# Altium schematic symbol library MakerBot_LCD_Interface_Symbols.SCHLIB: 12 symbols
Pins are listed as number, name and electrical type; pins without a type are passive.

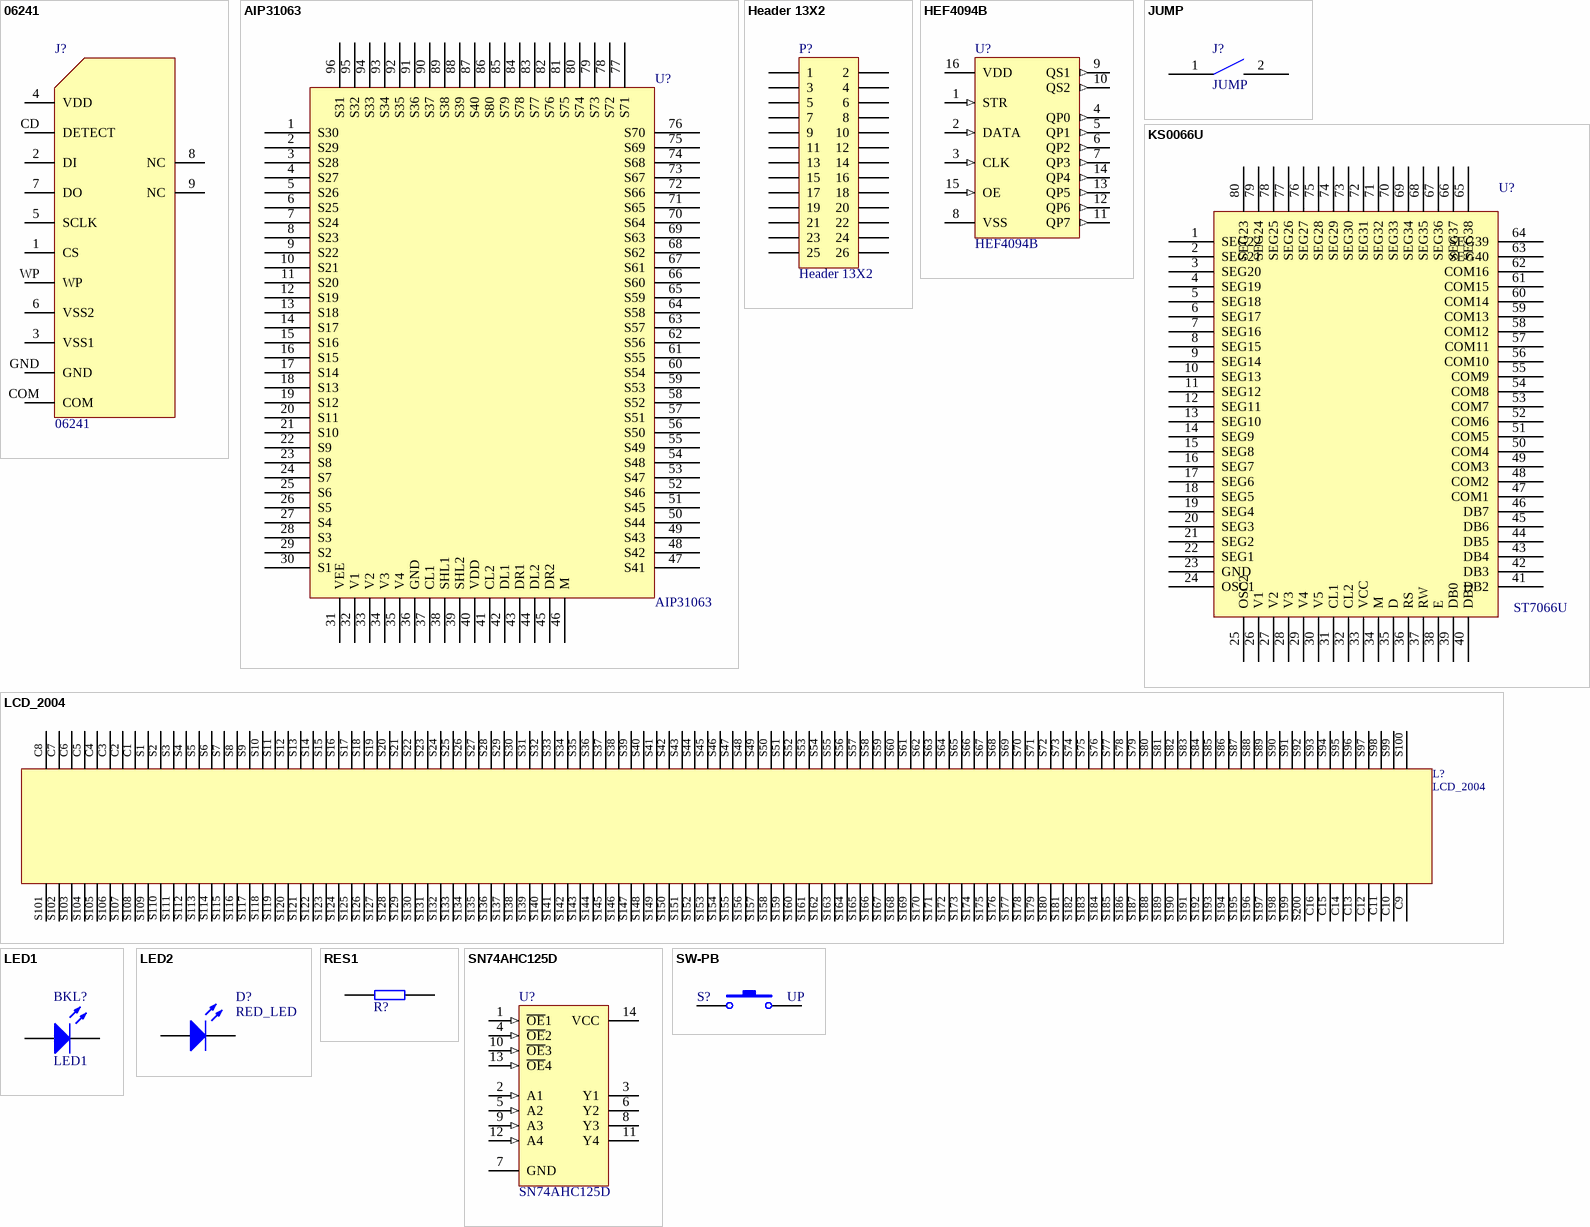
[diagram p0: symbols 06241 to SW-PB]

## 06241
designator J?
SD Card Slot, Push In / Push Out, Reverse
footprint 06241 (SD Card Slot, SMT, Push In / Push Out, Reverse Type)
pins: 1 CS, 2 DI, 3 VSS1, 4 VDD, 5 SCLK, 6 VSS2, 7 DO, 8 NC, 9 NC, CD DETECT, COM, GND, WP

## AIP31063
designator U?
footprint S6A2067
pins: 1 S30, 2 S29, 3 S28, 4 S27, 5 S26, 6 S25, 7 S24, 8 S23, 9 S22, 10 S21, 11 S20, 12 S19, 13 S18, 14 S17, 15 S16, 16 S15, 17 S14, 18 S13, 19 S12, 20 S11, 21 S10, 22 S9, 23 S8, 24 S7, 25 S6, 26 S5, 27 S4, 28 S3, 29 S2, 30 S1, 31 VEE, 32 V1, 33 V2, 34 V3, 35 V4, 36 GND, 37 CL1, 38 SHL1, 39 SHL2, 40 VDD, 41 CL2, 42 DL1, 43 DR1, 44 DL2, 45 DR2, 46 M, 47 S41, 48 S42, 49 S43, 50 S44, 51 S45, 52 S46, 53 S47, 54 S48, 55 S49, 56 S50, 57 S51, 58 S52, 59 S53, 60 S54, 61 S55, 62 S56, 63 S57, 64 S58, 65 S59, 66 S60, 67 S61, 68 S62, 69 S63, 70 S64, 71 S65, 72 S66, 73 S67, 74 S68, 75 S69, 76 S70, 77 S71, 78 S72, 79 S73, 80 S74, 81 S75, 82 S76, 83 S77, 84 S78, 85 S79, 86 S80, 87 S40, 88 S39, 89 S38, 90 S37, 91 S36, 92 S35, 93 S34, 94 S33, 95 S32, 96 S31

## Header 13X2
designator P?
Header, 13-Pin, Dual row
footprint HDR2X13 (Connector; Header; 13x2 Position)
signal-integrity model Connector
footprint 26-PIN SMT HEADER (26-PIN SMT Header,  0.1 IN., Vertical)
pins: 1, 2, 3, 4, 5, 6, 7, 8, 9, 10, 11, 12, 13, 14, 15, 16, 17, 18, 19, 20, 21, 22, 23, 24, 25, 26

## HEF4094B
designator U?
8-Stage Shift and Store Register
footprint SOIC127P602-16AN (SOIC, 16-Leads, Body 9.9x3.9mm, Pitch 1.27mm, IPC Medium Density)
pins: 1 STR (in), 2 DATA (in), 3 CLK (in), 4 QP0 (out), 5 QP1 (out), 6 QP2 (out), 7 QP3 (out), 8 VSS (power), 9 QS1 (out), 10 QS2 (out), 11 QP7 (out), 12 QP6 (out), 13 QP5 (out), 14 QP4 (out), 15 OE (in), 16 VDD (power)

## JUMP
designator J?
footprint JUMPER
footprint S1
footprint JUMP1
pins: 1, 2

## KS0066U
designator U?, comment ST7066U
footprint ST_7066
footprint S6A0069
pins: 1 SEG22, 2 SEG21, 3 SEG20, 4 SEG19, 5 SEG18, 6 SEG17, 7 SEG16, 8 SEG15, 9 SEG14, 10 SEG13, 11 SEG12, 12 SEG11, 13 SEG10, 14 SEG9, 15 SEG8, 16 SEG7, 17 SEG6, 18 SEG5, 19 SEG4, 20 SEG3, 21 SEG2, 22 SEG1, 23 GND, 24 OSC1, 25 OSC2, 26 V1, 27 V2, 28 V3, 29 V4, 30 V5, 31 CL1, 32 CL2, 33 VCC, 34 M, 35 D, 36 RS, 37 RW, 38 E, 39 DB0, 40 DB1, 41 DB2, 42 DB3, 43 DB4, 44 DB5, 45 DB6, 46 DB7, 47 COM1, 48 COM2, 49 COM3, 50 COM4, 51 COM5, 52 COM6, 53 COM7, 54 COM8, 55 COM9, 56 COM10, 57 COM11, 58 COM12, 59 COM13, 60 COM14, 61 COM15, 62 COM16, 63 SEG40, 64 SEG39, 65 SEG38, 66 SEG37, 67 SEG36, 68 SEG35, 69 SEG34, 70 SEG33, 71 SEG32, 72 SEG31, 73 SEG30, 74 SEG29, 75 SEG28, 76 SEG27, 77 SEG26, 78 SEG25, 79 SEG24, 80 SEG23

## LCD_2004
designator L?
footprint LCD_12232
footprint 2004A-GDS065W
pins: C1, C2, C3, C4, C5, C6, C7, C8, C9, C10, C11, C12, C13, C14, C15, C16, S1, S2, S3, S4, S5, S6, S7, S8, S9, S10, S11, S12, S13, S14, S15, S16, S17, S18, S19, S20, S21, S22, S23, S24, S25, S26, S27, S28, S29, S30, S31, S32, S33, S34, S35, S36, S37, S38, S39, S40, S41, S42, S43, S44, S45, S46, S47, S48, S49, S50, S51, S52, S53, S54, S55, S56, S57, S58, S59, S60, S61, S62, S63, S64, S65, S66, S67, S68, S69, S70, S71, S72, S73, S74, S75, S76, S77, S78, S79, S80, S81, S82, S83, S84, S85, S86, S87, S88, S89, S90, S91, S92, S93, S94, S95, S96, S97, S98, S99, S100, S101, S102, S103, S104, S105, S106, S107, S108, S109, S110, S111, S112, S113, S114, S115, S116, S117, S118, S119, S120, S121, S122, S123, S124, S125, S126, S127, S128, S129, S130, S131, S132, S133, S134, S135, S136, S137, S138, S139, S140, S141, S142, S143, S144, S145, S146, S147, S148, S149, S150, S151, S152, S153, S154, S155, S156, S157, S158, S159, S160, S161, S162, S163, S164, S165, S166, S167, S168, S169, S170, S171, S172, S173, S174, S175, S176, S177, S178, S179, S180, S181, S182, S183, S184, S185, S186, S187, S188, S189, S190, S191, S192, S193, S194, S195, S196, S197, S198, S199, S200

## LED1
designator BKL?
Typical RED GaAs LED
footprint LED-1 (Typical RED GaAs LED; 2 Leads)
simulation model LED1 (Diode)
footprint BKL (2004A LCD Backlight)
pins: 1 A, 2 K

## LED2
designator D?, comment RED_LED
Typical RED, GREEN, YELLOW, AMBER GaAs LED
footprint DSO-F2/D6.1 (SMT LED; 2 Flat Leads)
simulation model LED2 (Diode)
footprint 1206 LED, REVERSE (1206 SMT LED, REVERSE MOUNT)
pins: 1 A, 2 K

## RES1
designator R?  (value not drawn)
footprint 0805
footprint 1206
footprint 0805_B
footprint 0805_C
pins: 1, 2

## SN74AHC125D
designator U?
Quadruple Bus Buffer Gate with 3-State Outputs
footprint D014_N (SOIC, 14-Leads, Body 8.7x3.9mm, Pitch 1.27mm, IPC Medium Density)
footprint D014_L (SOIC, 14-Leads, Body 8.7x3.9mm, Pitch 1.27mm, IPC High Density)
footprint D014_M (SOIC, 14-Leads, Body 8.7x3.9mm, Pitch 1.27mm, IPC Low Density)
3D model D014 (14-Pin Small Outline Integrated Circuit 1.27 mm Pitch)
signal-integrity model SN74AHC125D
pins: 1 ~{OE}1 (in), 2 A1 (in), 3 Y1 (hiz), 4 ~{OE}2 (in), 5 A2 (in), 6 Y2 (hiz), 7 GND (power), 8 Y3 (hiz), 9 A3 (in), 10 ~{OE}3 (in), 11 Y4 (hiz), 12 A4 (in), 13 ~{OE}4 (in), 14 VCC (power)

## SW-PB
designator S?, comment UP
Switch
footprint SPST-2 (Switch; 2 Leads)
footprint 6mm Shorting Pad (6mm Shorting Pad for use with Silicone Button)
pins: 1, 2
